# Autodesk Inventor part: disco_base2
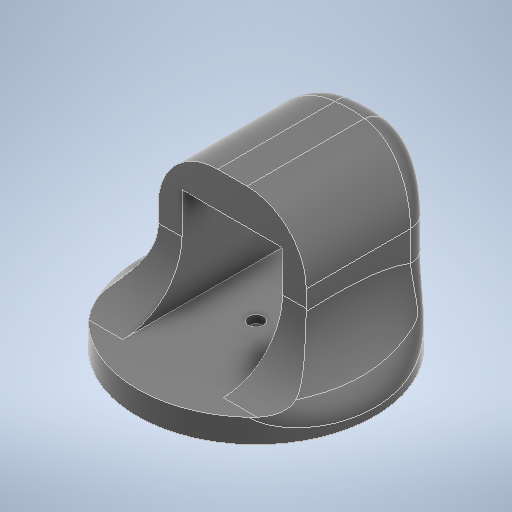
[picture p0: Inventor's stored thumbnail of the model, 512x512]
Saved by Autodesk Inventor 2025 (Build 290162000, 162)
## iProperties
Created: 2026-03
Part Number: disco_base2
Material: Plastica ABS
Document SubType Name: Modeling
Designer: R5800u
Density: 1.06 g/cm^3
Appearance: Liscia - Nero
Author: R5800u
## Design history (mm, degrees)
sketch "Schizzo1"
  geometry: C1 r 50 at (0, 0); 1 further point
  constraints: 1 centre point, 1 coincident
  dimensions: "d0" = 100 diameter of C1
extrude "Estrusione1" new body sketch "Schizzo1" distance "d1" = 10; taper "d2" = 0 deg
sketch "Schizzo2"
  geometry: C1 r 50 at (0, 0) reference; 3 further points
  constraints: 1 coincident
hole "Foro1" sketch "Schizzo2" at (0, 0) diameter "d3" = 3.4; stored, may be unused: countersink angle "d7" = 82 deg, drill point angle "d9" = 118 deg; dims "d4" = 6, "d5" = 6.5, "d6" = 3.4, "d8" = 8
sketch "Schizzo4"
  geometry: C1 r 1.6 at (-55, 30) reference; C2 r 1.6 at (-55, -30) reference; C3 r 1.6 at (55, -30) reference; C4 r 1.6 at (55, 30) reference; 1 further point
hole "Foro2" sketch "Schizzo4" at (-55, 30), (-55, -30), (55, 30), (55, -30) diameter "d14" = 4.3; stored, may be unused: countersink angle "d18" = 90 deg, drill point angle "d20" = 118 deg; dims "d15" = 6, "d16" = 7.5, "d17" = 3, "d19" = 8
sketch "Schizzo5"
  geometry: L1 (0, 0)-(0, -50); L2 (-21.2, -45.283)-(-21.2, 45.283); L3 (-21.2, -10)-(0, -10); L4 (21.2, -45.283)-(21.2, 45.283); L5 (21.2, -10)-(0, -10); L6 (-21.2, 45.283)-(21.2, 45.283); L7 (-31.2, -45.283)-(-31.2, 55.283); L8 (-31.2, 55.283)-(31.2, 55.283); L9 (31.2, 55.283)-(31.2, -45.283); L10 (-31.2, -10)-(31.2, -10); C1 r 1.7 at (0, 0) reference; A1 r 50 centre (0, 0) between (0, -50) and (-21.2, 45.283) reference; 7 further points
  constraints: 20 end point, 5 point on line, 3 point on circle, 3 symmetric about line, 2 perpendicular, 2 vertical, 1 horizontal, 2 other
  dimensions: "d22" = 21.2 distance between parallel lines of L1 L2; "d23" = 10 distance from line of point (0, 0) L3; "d24" = 10 distance between parallel lines of L2 L7
extrude "Estrusione3" join sketch "Schizzo5" distance "d25" = 42.2; taper "d26" = 0 deg
sketch "Schizzo6"
  geometry: L1 (31.2, -10)-(31.2, 39.071) reference; L2 (21.2, 45.283)-(21.2, -10) reference; L3 (21.2, -10)-(31.2, -10) reference; L4 (-21.2, -10)-(-21.2, 45.283) reference; L5 (-31.2, 39.071)-(-31.2, -10) reference; L6 (-31.2, -10)-(-21.2, -10) reference; L7 (21.2, -10)-(-21.2, -10); A1 r 50 centre (0, 0) between (31.2, 39.071) and (21.2, 45.283) reference; A2 r 50 centre (0, 0) between (21.2, 45.283) and (-21.2, 45.283) reference; A3 r 50 centre (0, 0) between (-21.2, 45.283) and (-31.2, 39.071) reference; 2 further points
  constraints: 2 end point, 1 horizontal
extrude "Estrusione4" join sketch "Schizzo6" distance "d27" = 15; taper "d28" = 0 deg
fillet "Raccordo3" dims "d29" = 25
fillet "Raccordo4" dims "d30" = 10
sketch "Schizzo7"
  geometry: C1 r 1.229 at (21.2, 21) reference; C2 r 5 at (21.2, 21); C3 r 1.621 at (21.2, 36) reference; C4 r 1.621 at (36.2, 21) reference; C5 r 1.621 at (6.2, 21) reference; C6 r 1.621 at (21.2, 6) reference; 1 further point
  constraints: 1 centre point, 1 coincident
  dimensions: "d31" = 10 diameter of C2
extrude "Estrusione5" cut sketch "Schizzo7" extent not by distance; stored distance "d32" = 0; taper "d33" = 0 deg
node "Piano di lavoro1"
sketch "Schizzo8"
  geometry: 10 further points
  constraints: 1 coincident, 1 horizontal alignment, 4 other
hole "Foro3" sketch "Schizzo8" diameter "d34" = 4.5; stored, may be unused: countersink angle "d38" = 90 deg, drill point angle "d40" = 118 deg; dims "d35" = 6, "d36" = 7, "d37" = 1, "d39" = 8
hole "Foro4" sketch "Schizzo8" diameter "d41" = 4.5; stored, may be unused: countersink angle "d45" = 90 deg, drill point angle "d47" = 118 deg; dims "d42" = 6, "d43" = 7, "d44" = 3, "d46" = 8
node "Solido1"
node "Riferimento5"
node "Riferimento6"
node "Riferimento7"
node "Riferimento8"
node "Linea chiusa proiettata2"
node "Linea chiusa proiettata3"
node "Riferimento9"
node "Riferimento10"
node "Riferimento11"
node "Riferimento12"
node "Riferimento13"
